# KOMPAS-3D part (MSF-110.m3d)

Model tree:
1. Ось X
2. Ось Y
3. Ось Z
4. Начало координат  (labels: Операция без истории:1)

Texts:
  Линия-выноска #1
  Линия-выноска #2
  Линия-выноска #3
  Отклонения формы и база
  Марка координационной оси
  Марка/позиционное обозначение с линией-выноской
  Марка/позиционное обозначение на линии
  Марка/позиционное обозначение без линии-выноски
